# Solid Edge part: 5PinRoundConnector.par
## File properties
Author: conerly
Template: ansi part.par
Last saved by: alogan
Revision: 24
Application: Solid Edge
Density: 0.0979772159 lbm/in^3
Accuracy: 0.990
FromName: Batt(-)
Material: Aluminum, 1060
Face Style: Aluminum
Fill Style: ANSI38(Aluminum)
Virtual Style: Polished aluminum
Coef. of Thermal Exp: 2.3e-05
Thermal Conductivity: 221.0
Specific Heat: 920.0
Modulus of Elasticity: 68947570000.0
Poisson's Ratio: 0.33
Yield Stress: 27579028.0
Ultimate Stress: 68947570.0
Elongation: 0.0
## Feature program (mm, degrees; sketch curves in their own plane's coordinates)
sketch for "unnamed Protrusion 1" plane through (10.8687, 0, 10.8687) normal (0, -1, 0) x-axis (1, 0, 0)
  circle centre (-10.8687, -10.8687) radius 6.35
extrude "unnamed Protrusion 1" add finite 12.7 along -normal
sketch for "ExtrudedCutout_1" #1 plane through (0, 0, 0) normal (0, -1, 0) x-axis (1, 0, 0)
  circle centre (0, 0) radius 0.7937
sketch for "ExtrudedCutout_1" #2 plane through (0, 0, 0) normal (0, -1, 0) x-axis (1, 0, 0)
  circle centre (0, 4.064) radius 0.8599
extrude "ExtrudedCutout_1" cut finite 1.5748 along -normal
pattern "unnamed Pattern 1" of "ExtrudedCutout_1"
extrude "unnamed Cutout 1" cut finite 1.5748
extrude "unnamed Cutout 2" cut finite 1.5748
extrude "unnamed Cutout 3" cut finite 1.5748
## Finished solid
Body 1: solid body, 13 faces, 12 edges, 0 vertices.
  Faces by surface: plane 7, cylinder 6
  Edges by curve: circle 12
Bounding box of the edges (mm): 12.700 x 12.700 x 12.700, from (-6.35, 0, -6.35) to (6.35, 12.7, 6.35).
Cylindrical faces by radius (mm): R0.7937 x1, R0.8599 x4, R6.35 x1
Planar faces by outward normal: +y 1, -y 6
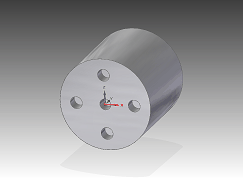
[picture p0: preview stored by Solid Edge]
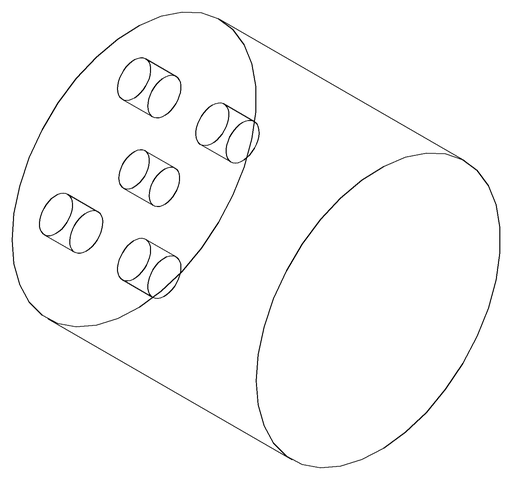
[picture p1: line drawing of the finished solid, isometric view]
